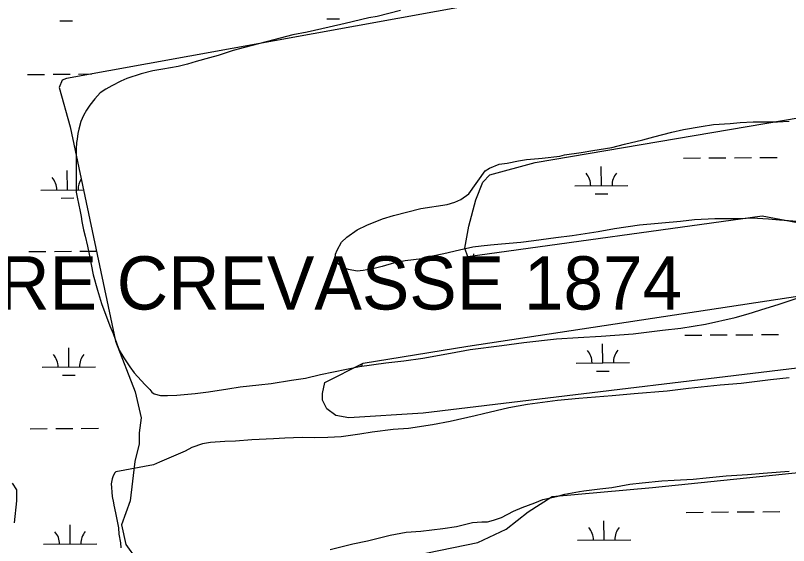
# Model space of a CAD drawing. Extents: x 3540316 to 3578335, y 553172 to 578787.
# Drawn here: x 3555162 to 3556615, y 563355 to 564350 of the extents above; entities that cross this region are included whole.
import ezdxf

# ---------------------------------------------------------------- set-up
doc = ezdxf.new("R2010")
doc.units = 0
for name, color, linetype in [('V-RIVR-IDEN', 7, 'Continuous'), ('V-SITE-VEGE', 7, 'Continuous'), ('V-WETL-SWMP', 7, 'Continuous')]:
    doc.layers.add(name, color=color, linetype=linetype)

msp = doc.modelspace()

# ---------------------------------------------------------------- linework, layer by layer
at = {"layer": 'V-SITE-VEGE'}
for points in [[(3555886.2, 564359.7), (3555842, 564348.5), (3555826.5, 564345.8), (3555781.7, 564335.1), (3555751.8, 564328.2), (3555710.4, 564319.1), (3555683.8, 564313.8), (3555647.9, 564304.7), (3555592.6, 564290.2), (3555571.5, 564284.3), (3555543.3, 564275.1), (3555526.7, 564270.8), (3555501.8, 564263.8), (3555485.2, 564259), (3555468.1, 564254.7), (3555439.4, 564249.4), (3555420.6, 564246.2), (3555398.4, 564240.9), (3555371.3, 564231.7), (3555360.2, 564226.8), (3555343.1, 564218.1), (3555332, 564212.1), (3555321.4, 564205), (3555311.4, 564193.5), (3555301.9, 564182), (3555295.8, 564172.6), (3555290.2, 564162.2), (3555285.2, 564151.2), (3555281.2, 564136.8), (3555279.5, 564128.6), (3555278.3, 564118.1), (3555277.1, 564111.5), (3555276.5, 564099.9), (3555276, 564032), (3555276.5, 564024.8), (3555276.4, 564018.2), (3555278, 564008.8), (3555281.2, 563993.9), (3555282.8, 563985), (3555285.5, 563972.9), (3555287.1, 563963.5), (3555290.2, 563947.4), (3555292.9, 563935.8), (3555297.7, 563917)], [(3555763.5, 563901.9), (3555766.9, 563909.6), (3555775.3, 563924.5), (3555784.8, 563933.8), (3555804.7, 563947.4), (3555822.5, 563956.7), (3555852.4, 563968.6), (3555872.8, 563974.5), (3555924.3, 563987.9), (3555973.5, 563995.3), (3555988.4, 563999.6), (3555999.5, 564004.5), (3556014.5, 564015.4), (3556045.1, 564058.2), (3556053.5, 564063.7), (3556071.7, 564070.7), (3556086.7, 564072.8), (3556107.7, 564077.1), (3556122.6, 564079.8), (3556145.2, 564081.8), (3556152.4, 564082.3), (3556185.6, 564085.9), (3556194.4, 564088.6), (3556225.4, 564092.8), (3556247.5, 564096.5), (3556283.4, 564102.3), (3556307.2, 564108.7), (3556341.5, 564116.8), (3556362.5, 564122.1), (3556396.2, 564131.2), (3556417.8, 564136.1), (3556451.5, 564141.9), (3556474.2, 564145.6), (3556505.7, 564147.5), (3556524.4, 564149.1), (3556549.3, 564150.5), (3556580.8, 564150.3), (3556594.6, 564150.7), (3556616.6, 564151.7)], [(3556632.4, 563963.3), (3556598.7, 563965.8), (3556577.7, 563967.6), (3556546.3, 563969.5), (3556525.3, 563968.5), (3556490, 563968.2), (3556476.7, 563968.3), (3556438.6, 563966.4), (3556412.1, 563963.3), (3556335.3, 563956.2), (3556288.3, 563949.3), (3556257.4, 563944), (3556208.7, 563936.7), (3556178.3, 563932.5), (3556136.4, 563927.3), (3556112, 563923.6), (3556076.1, 563920.6), (3556055.1, 563919.1), (3556037.5, 563917), (3556022, 563914.9), (3555996.6, 563909.6), (3555967.2, 563902.6), (3555946.2, 563898.4), (3555925.8, 563893.5), (3555894.8, 563889.4), (3555874.9, 563885.6), (3555851.7, 563878.6), (3555836.2, 563874.9), (3555815.8, 563871.2), (3555804.7, 563870.2), (3555788.2, 563873), (3555777.7, 563877), (3555766.7, 563884.8), (3555763.5, 563889.2), (3555762.9, 563894.8), (3555763.5, 563901.9)], [(3555297.7, 563917), (3555300.4, 563902.1), (3555308.4, 563863.4), (3555316.4, 563834.1), (3555324, 563809.2), (3555339.7, 563767.7), (3555345.6, 563752.7), (3555352.7, 563733.3), (3555357, 563721.7), (3555365.7, 563707.3), (3555377.2, 563690.6), (3555385.4, 563679), (3555405.1, 563657.3), (3555414.4, 563647.9), (3555418.2, 563642.9), (3555422.6, 563639.5), (3555434.8, 563636.7), (3555448, 563636.6), (3555465.7, 563637), (3555499.9, 563640.6), (3555525.3, 563643.7), (3555561.3, 563649), (3555584.5, 563652.7), (3555619.8, 563656.3), (3555643, 563659.4), (3555681.2, 563665.2), (3555707.2, 563669.4), (3555735.4, 563675.8), (3555808.9, 563691.3), (3555858.1, 563698.1), (3555892.3, 563701.7), (3555927.7, 563706.9), (3555980.2, 563715.9), (3556016.7, 563722.8), (3556076.4, 563730.7), (3556117.8, 563735.9), (3556179.1, 563743.1), (3556220, 563745.6), (3556263.1, 563748), (3556323.3, 563752.5), (3556378.5, 563759.3), (3556412.8, 563762.9), (3556459.2, 563770.8), (3556515.1, 563783.1), (3556539.4, 563790.1), (3556573.7, 563800.4), (3556595.8, 563807.4), (3556629.6, 563818.7)], [(3556616.9, 563669.7), (3556581.5, 563666.2), (3556526.3, 563659.4), (3556487.1, 563655.8), (3556427.4, 563649.6), (3556387.6, 563645), (3556325.2, 563639.4)], [(3556325.2, 563639.4), (3556283.8, 563635.8), (3556221.4, 563630.8), (3556181, 563627.2), (3556124.7, 563619.9), (3556089.8, 563613.5), (3556041.7, 563602.3), (3556026.2, 563598.6), (3555979.2, 563587.9), (3555946.1, 563581.5), (3555900.8, 563574.7), (3555872, 563572.7), (3555832.8, 563567.4), (3555809.6, 563563.7), (3555774.2, 563559), (3555749.4, 563557.6), (3555725.1, 563557.2), (3555700.8, 563557.4), (3555668.2, 563556.5), (3555647.2, 563555), (3555606.4, 563553.1), (3555576, 563550.6), (3555555.6, 563550.2), (3555528.5, 563548.2), (3555513.6, 563545.5), (3555493.6, 563539.1), (3555481.4, 563532), (3555454.9, 563520.6), (3555432.7, 563511.4), (3555421.6, 563506.5), (3555350.9, 563493.2), (3555349.2, 563491.6), (3555345.8, 563485.5), (3555343.6, 563480), (3555341.9, 563470.6), (3555342.4, 563464), (3555343.4, 563455.2), (3555343.9, 563446.9), (3555346.6, 563435.3), (3555347.1, 563430.9), (3555350.3, 563415.9), (3555355.6, 563388.3), (3555356.6, 563376.1), (3555359.3, 563359.6), (3555360.3, 563350.7)], [(3555753.9, 563347.2), (3555796.5, 563357.9), (3555824.1, 563363.8), (3555866.7, 563374.5), (3555896.5, 563379.8), (3555924.1, 563381.8), (3555965.6, 563387), (3555991, 563390.7), (3556021.4, 563398.2), (3556039.1, 563399.2), (3556049.6, 563399.1), (3556060.7, 563402.3), (3556076.1, 563407.7), (3556098.3, 563419.2), (3556114.9, 563426.2), (3556138.2, 563434.9), (3556153.7, 563441.4), (3556179.1, 563446.7), (3556195.2, 563451), (3556222.2, 563456.3), (3556230.5, 563457.4), (3556260.9, 563461.5), (3556283, 563463.6), (3556317.3, 563470), (3556340, 563472.5), (3556377, 563476.1), (3556400.7, 563477.6), (3556436.1, 563479.6), (3556460.4, 563482.1), (3556498.5, 563485.7), (3556538.3, 563488.2), (3556567.5, 563490.7), (3556616.7, 563494.2)]]:
    msp.add_lwpolyline(points, dxfattribs=at)
at = {"layer": 'V-WETL-SWMP'}
for p, q in [((3555245.4, 564339.9), (3555269.4, 564340.1)), ((3555747.3, 564343.8), (3555771.3, 564344)), ((3555184.7, 564239.5), (3555216.7, 564239.7)), ((3555232.7, 564239.8), (3555264.7, 564240.1)), ((3555280.7, 564240.2), (3555305.7, 564240.4)), ((3556417.8, 564082.5), (3556449.8, 564082.7)), ((3556465.8, 564082.8), (3556497.8, 564083.1)), ((3556513.8, 564083.2), (3556545.8, 564083.5)), ((3556561.8, 564083.6), (3556593.8, 564083.8)), ((3556263.6, 564030.5), (3556263.3, 564066.5)), ((3555259.8, 564022.8), (3555259.5, 564058.8)), ((3555209.8, 564022.4), (3555289.9, 564023)), ((3556213.6, 564030.2), (3556313.6, 564030.9)), ((3555247.9, 564007.3), (3555271.9, 564007.5)), ((3556251.7, 564015), (3556275.7, 564015.2)), ((3555187.3, 563906.8), (3555219.3, 563907.1)), ((3555235.3, 563907.2), (3555267.3, 563907.4)), ((3555283.3, 563907.5), (3555314.4, 563907.8)), ((3556024.1, 563898.4), (3556024.1, 563902.8)), ((3556420.4, 563749.8), (3556452.4, 563750.1)), ((3556468.4, 563750.2), (3556500.4, 563750.4)), ((3556516.4, 563750.5), (3556548.4, 563750.8)), ((3556564.4, 563750.9), (3556596.4, 563751.2)), ((3556266.2, 563697.9), (3556265.9, 563733.9)), ((3555262.4, 563690.1), (3555262.1, 563726.1)), ((3556216.2, 563697.5), (3556316.2, 563698.3)), ((3555212.4, 563689.8), (3555312.4, 563690.5)), ((3555810.1, 563694.4), (3555814.3, 563694.4)), ((3555250.5, 563674.6), (3555274.5, 563674.8)), ((3556254.3, 563682.4), (3556278.3, 563682.5)), ((3555189.9, 563574.1), (3555221.9, 563574.4)), ((3555237.9, 563574.5), (3555269.9, 563574.8)), ((3555285.9, 563574.9), (3555317.9, 563575.1)), ((3556422.9, 563417.1), (3556454.9, 563417.4)), ((3556470.9, 563417.5), (3556502.9, 563417.8)), ((3556518.9, 563417.9), (3556550.9, 563418.1)), ((3556566.9, 563418.3), (3556598.9, 563418.5)), ((3555264.9, 563357.5), (3555264.7, 563393.5)), ((3556268.7, 563365.2), (3556268.5, 563401.2)), ((3556218.7, 563364.8), (3556318.7, 563365.6)), ((3555214.9, 563357.1), (3555314.9, 563357.9))]:
    msp.add_line(p, q, dxfattribs=at)
for points in [[(3556033.1, 564372.2), (3555258, 564231.8), (3555249.8, 564228.9), (3555244.5, 564215.1), (3555264.8, 564141.3), (3555350.3, 563738.8), (3555387.4, 563643.3), (3555398.5, 563594.9), (3555394.4, 563566.2), (3555394.4, 563545.6), (3555386.2, 563512.8), (3555378, 563438.8), (3555361.6, 563393.6), (3555369.8, 563356.7), (3555390.3, 563327.9)], [(3556632.2, 563960.8), (3556566.1, 563973.5), (3556012.6, 563896.8), (3556006.8, 563913.2), (3556014.5, 563954.5), (3556027.5, 564004.1), (3556040.7, 564037.3), (3556054.2, 564051.2), (3556139, 564074.4), (3556670.4, 564164.5)], [(3555815.6, 563697.2), (3556012.3, 563729.3), (3556637, 563823.5)], [(3556782.9, 563705.8), (3555928.5, 563603.1), (3555788.8, 563594.9), (3555764.1, 563599), (3555747.7, 563611.4), (3555739.5, 563627.8), (3555739.5, 563640.1), (3555743.6, 563660.7), (3555815.6, 563697.2)], [(3555912, 563336.1), (3556031.2, 563360.8), (3556084.6, 563385.4), (3556125.7, 563418.3), (3556170.8, 563447), (3556359.8, 563463.5), (3556713.1, 563500.4)], [(3555160.3, 563397.7), (3555164.4, 563438.8), (3555164.4, 563459.4), (3555156.2, 563471.7)]]:
    msp.add_lwpolyline(points, dxfattribs=at)
for centre, start, end in [((3556208.4, 564030.6), 359.6699, 41.2135), ((3556318.8, 564031.4), 139.6698, 181.2135), ((3555204.6, 564022.9), 359.6699, 41.2135), ((3555315.1, 564023.7), 146.4758, 181.2135), ((3555207.1, 563690.2), 359.6699, 41.2135), ((3555317.6, 563691), 139.6698, 181.2135), ((3556210.9, 563697.9), 359.6699, 41.2135), ((3556321.4, 563698.8), 139.6698, 181.2135), ((3555209.7, 563357.5), 359.6699, 41.2135), ((3555320.2, 563358.4), 139.6698, 181.2135), ((3556213.5, 563365.3), 359.6699, 41.2135), ((3556324, 563366.1), 139.6698, 181.2135)]:
    msp.add_arc(centre, 35.2, start, end, dxfattribs=at)

# ---------------------------------------------------------------- texts
at = {"layer": 'V-RIVR-IDEN'}
msp.add_text('BONNET CARRE CREVASSE 1874', height=100, dxfattribs=at).set_placement((3554252.9, 563798))

doc.saveas('drawing.dxf')
